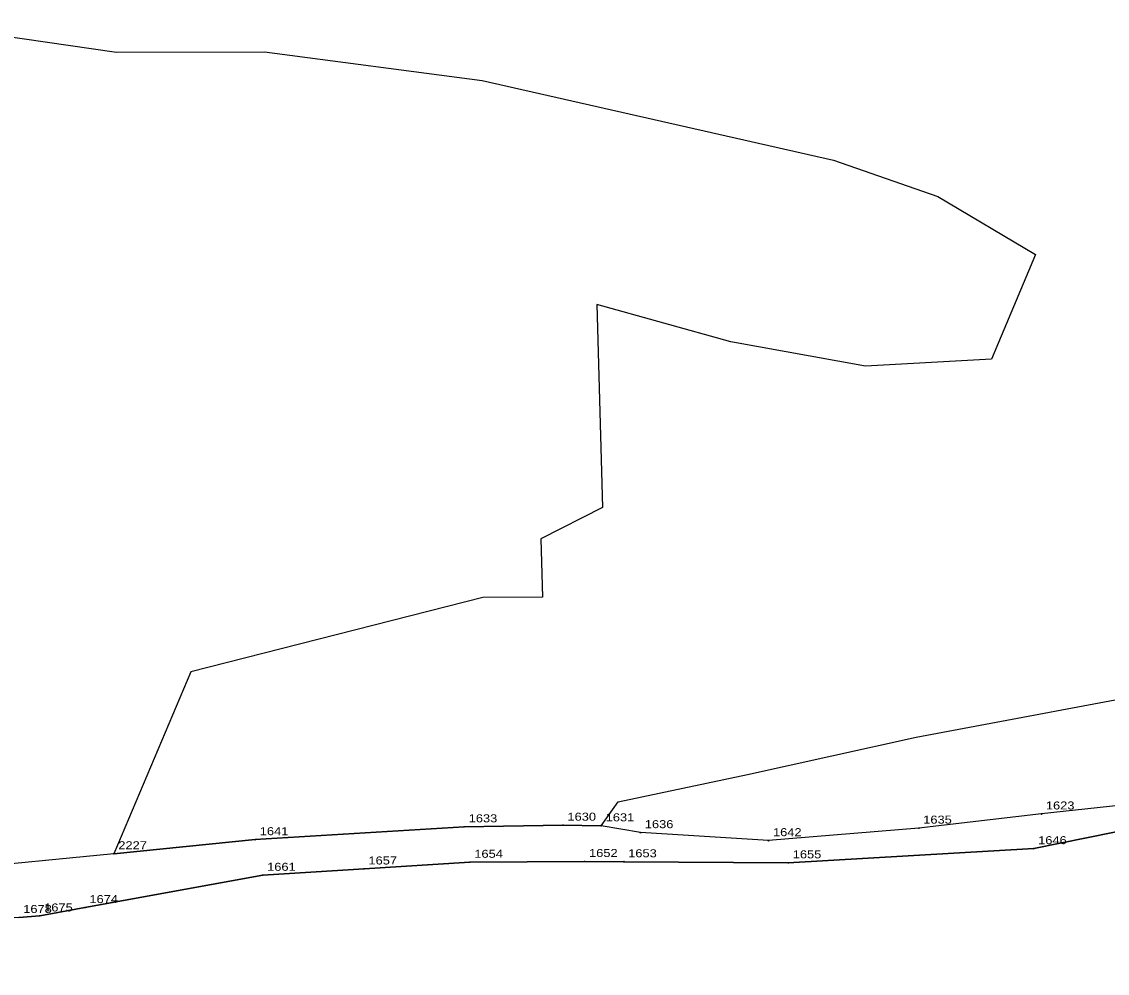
# Model space of a CAD drawing. Extents: x 4640203 to 4641683, y 5358965 to 5360242.
# Drawn here: x 4640696.6 to 4640818.7, y 5360016 to 5360122.9 of the extents above; entities that cross this region are included whole.
import ezdxf

# ---------------------------------------------------------------- set-up
doc = ezdxf.new("R2010")
doc.units = 0
doc.header["$LTSCALE"] = 0.36
for name, color, linetype, lineweight in [('25', 7, 'Continuous', 25), ('27', 7, 'Continuous', 25), ('8', 7, 'Continuous', 25)]:
    doc.layers.add(name, color=color, linetype=linetype, lineweight=lineweight)

msp = doc.modelspace()

# ---------------------------------------------------------------- linework, layer by layer
at = {"layer": '25'}
for points in [[(4640827.98, 5360035.67), (4640811.29, 5360033.86), (4640797.5, 5360032.27), (4640780.61, 5360030.86), (4640766.2, 5360031.76), (4640761.8, 5360032.53), (4640757.5, 5360032.6), (4640746.4, 5360032.42), (4640722.91, 5360030.97), (4640707.01, 5360029.39), (4640689.33, 5360027.64), (4640672.34, 5360026.52), (4640663.03, 5360027.26), (4640637.55, 5360039.39), (4640625.49, 5360048.81), (4640616.65, 5360054.35), (4640576.84, 5360055.38)], [(4640696.32, 5360022.23), (4640698.67, 5360022.4), (4640703.76, 5360023.34), (4640723.74, 5360026.97), (4640735.13, 5360027.68), (4640747.03, 5360028.43), (4640759.93, 5360028.52), (4640764.33, 5360028.49), (4640782.83, 5360028.37), (4640810.42, 5360029.96), (4640828.19, 5360033.58)]]:
    msp.add_lwpolyline(points, dxfattribs=at)
at = {"layer": '27'}
for points in [[(4640683.74, 5360122.89), (4640707.3, 5360119.47), (4640723.94, 5360119.51), (4640748.42, 5360116.28), (4640787.91, 5360107.34), (4640799.63, 5360103.26), (4640810.63, 5360096.72), (4640805.68, 5360084.96), (4640791.52, 5360084.18), (4640776.36, 5360086.9), (4640761.3, 5360091.12), (4640761.94, 5360068.31), (4640755.01, 5360064.77)], [(4640755.01, 5360064.77), (4640755.2, 5360058.23), (4640748.48, 5360058.18), (4640715.67, 5360049.82), (4640707.01, 5360029.39), (4640722.91, 5360030.97), (4640746.4, 5360032.42), (4640757.5, 5360032.6), (4640761.8, 5360032.53), (4640763.71, 5360035.22), (4640778.24, 5360038.31), (4640797.19, 5360042.47), (4640827.97, 5360048.27), (4640839.03, 5360054.05), (4640856.15, 5360057.79), (4640867.92, 5360046.79)], [(4640707.01, 5360029.39), (4640689.33, 5360027.64), (4640672.34, 5360026.52), (4640663.03, 5360027.26), (4640637.55, 5360039.39), (4640625.49, 5360048.81), (4640616.65, 5360054.35), (4640576.84, 5360055.38), (4640560.72, 5360055.73), (4640536.93, 5360058.21), (4640523.61, 5360059.87), (4640507.4, 5360062.51), (4640473.7, 5360062.18), (4640456.6, 5360062.07), (4640436.47, 5360062.36), (4640433.09, 5360063.11), (4640421.87, 5360051.33)], [(4640888.85, 5360025.39), (4640875.93, 5360028.6), (4640844.78, 5360035.79), (4640827.98, 5360035.67), (4640811.29, 5360033.86), (4640797.5, 5360032.27), (4640780.61, 5360030.86), (4640766.2, 5360031.76), (4640761.8, 5360032.53)], [(4640904.69, 5360018.38), (4640888.57, 5360022.18), (4640879.12, 5359986.05), (4640856.44, 5359988.67), (4640836.58, 5359990.96), (4640835.87, 5360009.69), (4640835.91, 5360014.37), (4640835.89, 5360016.46), (4640835.72, 5360033.46), (4640834.19, 5360033.52), (4640828.19, 5360033.58), (4640810.42, 5360029.96), (4640782.83, 5360028.37), (4640764.33, 5360028.49), (4640759.93, 5360028.52), (4640747.03, 5360028.43), (4640735.13, 5360027.68), (4640723.74, 5360026.97), (4640703.76, 5360023.34), (4640698.67, 5360022.4), (4640696.32, 5360022.23), (4640670.28, 5360020.31), (4640655.62, 5359984.88), (4640641.2, 5359946.4)]]:
    msp.add_lwpolyline(points, dxfattribs=at)
at = {"layer": '8'}
for centre in [(4640811.29, 5360033.86), (4640746.4, 5360032.42), (4640757.5, 5360032.6), (4640761.8, 5360032.53), (4640797.5, 5360032.27), (4640722.91, 5360030.97), (4640766.2, 5360031.76), (4640780.61, 5360030.86), (4640810.42, 5360029.96), (4640707.01, 5360029.39), (4640747.03, 5360028.43), (4640759.93, 5360028.52), (4640764.33, 5360028.49), (4640782.83, 5360028.37), (4640735.13, 5360027.68), (4640723.74, 5360026.97), (4640698.67, 5360022.4), (4640703.76, 5360023.34)]:
    msp.add_circle(centre, 0.045, dxfattribs=at)

# ---------------------------------------------------------------- texts
at = {"layer": '8', "width": 1.2}
for s, p in [('1623', (4640811.79, 5360034.36)), ('1633', (4640746.9, 5360032.92)), ('1630', (4640758, 5360033.1)), ('1631', (4640762.3, 5360033.03)), ('1635', (4640798, 5360032.77)), ('1641', (4640723.41, 5360031.47)), ('1636', (4640766.7, 5360032.26)), ('1642', (4640781.11, 5360031.36)), ('1646', (4640810.92, 5360030.46)), ('2227', (4640707.51, 5360029.89)), ('1654', (4640747.53, 5360028.93)), ('1652', (4640760.43, 5360029.02)), ('1653', (4640764.83, 5360028.99)), ('1655', (4640783.33, 5360028.87)), ('1657', (4640735.63, 5360028.18)), ('1661', (4640724.24, 5360027.47)), ('1674', (4640704.26, 5360023.84)), ('1678', (4640696.82, 5360022.73)), ('1675', (4640699.17, 5360022.9))]:
    msp.add_text(s, height=0.9, dxfattribs=at).set_placement(p)

doc.saveas('drawing.dxf')
